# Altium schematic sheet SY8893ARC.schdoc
size 127 x 101 mm
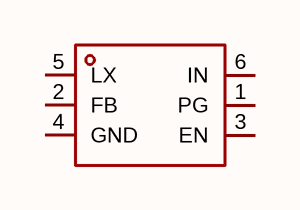
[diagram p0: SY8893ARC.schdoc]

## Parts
U?  sy8893arc  [SOT-563-6_L1.6-W1.2-P0.5-LS1.6-BL]  (value not drawn)

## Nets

Not connected (* = marked no-connect by the designer): U? 1(PG) 2(FB) 3(EN) 4(GND) 5(LX) 6(IN)

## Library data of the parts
U? = sy8893arc: 功能类型:降压型;工作电压:2.5V~5.5V;输出电压:-;输出电流:3A;输出类型:可调;; Manufacturer: Silergy(矽力杰); AddInBom: yes; ModelId: 6c48915c55ca481897faee5dfab5b527; ModelTransform: 62.992,62.992,0,0,0,0,0,0,0; Function: 降压型; Output Current: 3A; Frequency - Switching: 1.2MHz; Synchronous Rectifier: 是; Number of Outputs: 1; Topology: 降压式; Quiescent Current: 50uA; Switch tube (built-in/external): 内置; Output Type: 可调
